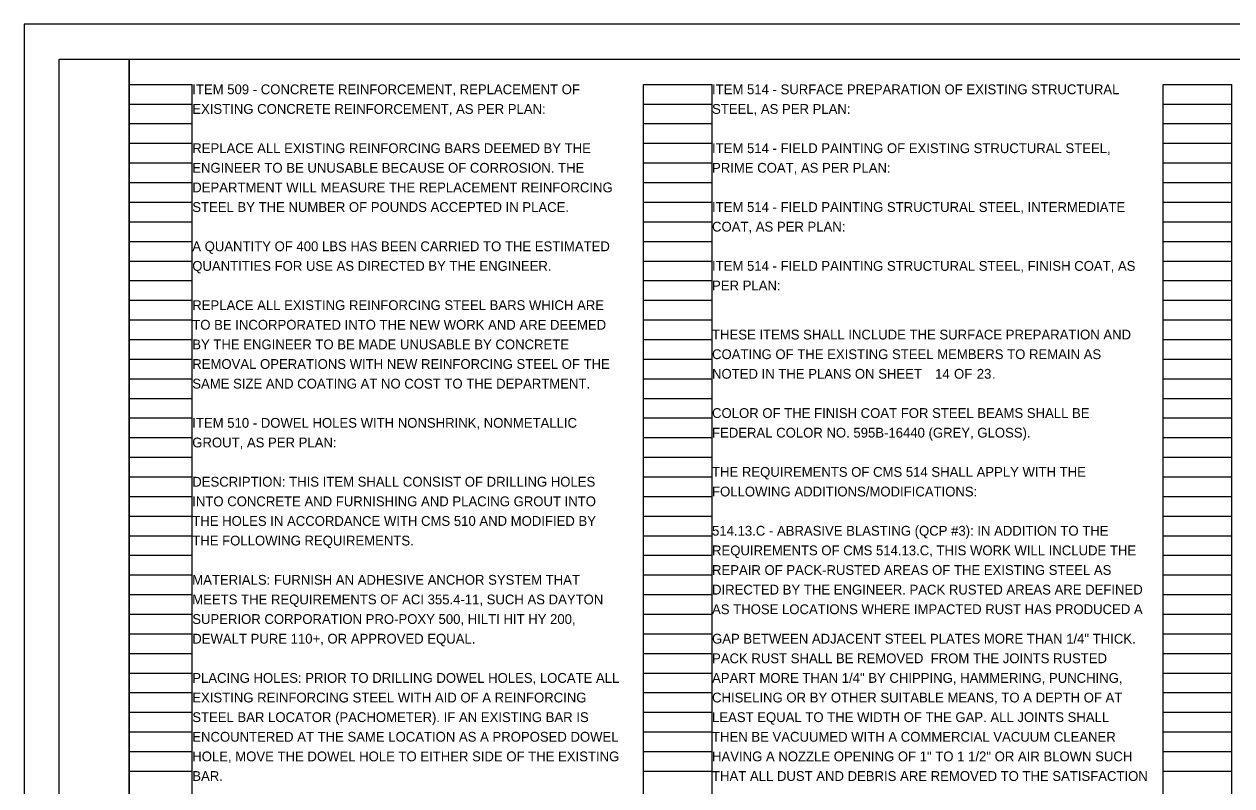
# Model space of a CAD drawing. Extents: x 0 to 34, y 0 to 22.
# Drawn here: x 0 to 17.24, y 11.13 to 22 of the extents above; entities that cross this region are included whole.
import ezdxf

# ---------------------------------------------------------------- set-up
doc = ezdxf.new("R2010")
doc.units = 0
for name, color, linetype in [('BR_P_Gen_Text', 7, 'Continuous'), ('SH_Border', 7, 'Continuous'), ('SH_Cut_Line', 7, 'Continuous'), ('SH_Data', 7, 'Continuous')]:
    doc.layers.add(name, color=color, linetype=linetype)

msp = doc.modelspace()

# ---------------------------------------------------------------- linework, layer by layer
at = {"layer": 'SH_Border'}
for points in [[(0.5, 21.5), (1.5, 21.5), (1.5, 0.5), (0.5, 0.5)], [(1.5, 21.5), (33.5, 21.5), (33.5, 0.5), (1.5, 0.5)]]:
    msp.add_lwpolyline(points, close=True, dxfattribs=at)
at = {"layer": 'SH_Cut_Line'}
msp.add_lwpolyline([(0, 0), (34, 0), (34, 22), (0, 22)], close=True, dxfattribs=at)
at = {"layer": 'SH_Data'}
for p, q in [((1.5, 0.98), (1.5, 21.14)), ((1.5, 21.14), (2.4, 21.14)), ((2.4, 0.98), (2.4, 21.14)), ((8.84, 0.98), (8.84, 21.14)), ((8.84, 21.14), (9.82, 21.14)), ((9.82, 0.98), (9.82, 21.14)), ((16.26, 0.98), (16.26, 21.14)), ((16.26, 21.14), (17.24, 21.14)), ((17.24, 0.98), (17.24, 21.14)), ((1.5, 20.86), (2.4, 20.86)), ((8.84, 20.86), (9.82, 20.86)), ((16.26, 20.86), (17.24, 20.86)), ((1.5, 20.58), (2.4, 20.58)), ((8.84, 20.58), (9.82, 20.58)), ((16.26, 20.58), (17.24, 20.58)), ((1.5, 20.3), (2.4, 20.3)), ((8.84, 20.3), (9.82, 20.3)), ((16.26, 20.3), (17.24, 20.3)), ((1.5, 20.02), (2.4, 20.02)), ((8.84, 20.02), (9.82, 20.02)), ((16.26, 20.02), (17.24, 20.02)), ((1.5, 19.74), (2.4, 19.74)), ((8.84, 19.74), (9.82, 19.74)), ((16.26, 19.74), (17.24, 19.74)), ((1.5, 19.46), (2.4, 19.46)), ((8.84, 19.46), (9.82, 19.46)), ((16.26, 19.46), (17.24, 19.46)), ((1.5, 19.18), (2.4, 19.18)), ((8.84, 19.18), (9.82, 19.18)), ((16.26, 19.18), (17.24, 19.18)), ((1.5, 18.9), (2.4, 18.9)), ((8.84, 18.9), (9.82, 18.9)), ((16.26, 18.9), (17.24, 18.9)), ((1.5, 18.62), (2.4, 18.62)), ((8.84, 18.62), (9.82, 18.62)), ((16.26, 18.62), (17.24, 18.62)), ((1.5, 18.34), (2.4, 18.34)), ((8.84, 18.34), (9.82, 18.34)), ((16.26, 18.34), (17.24, 18.34)), ((1.5, 18.06), (2.4, 18.06)), ((8.84, 18.06), (9.82, 18.06)), ((16.26, 18.06), (17.24, 18.06)), ((1.5, 17.78), (2.4, 17.78)), ((8.84, 17.78), (9.82, 17.78)), ((16.26, 17.78), (17.24, 17.78)), ((1.5, 17.5), (2.4, 17.5)), ((8.84, 17.5), (9.82, 17.5)), ((16.26, 17.5), (17.24, 17.5)), ((1.5, 17.22), (2.4, 17.22)), ((8.84, 17.22), (9.82, 17.22)), ((16.26, 17.22), (17.24, 17.22)), ((1.5, 16.94), (2.4, 16.94)), ((8.84, 16.94), (9.82, 16.94)), ((16.26, 16.94), (17.24, 16.94)), ((1.5, 16.66), (2.4, 16.66)), ((8.84, 16.66), (9.82, 16.66)), ((16.26, 16.66), (17.24, 16.66)), ((1.5, 16.38), (2.4, 16.38)), ((8.84, 16.38), (9.82, 16.38)), ((16.26, 16.38), (17.24, 16.38)), ((1.5, 16.1), (2.4, 16.1)), ((8.84, 16.1), (9.82, 16.1)), ((16.26, 16.1), (17.24, 16.1)), ((1.5, 15.82), (2.4, 15.82)), ((8.84, 15.82), (9.82, 15.82)), ((16.26, 15.82), (17.24, 15.82)), ((1.5, 15.54), (2.4, 15.54)), ((8.84, 15.54), (9.82, 15.54)), ((16.26, 15.54), (17.24, 15.54)), ((1.5, 15.26), (2.4, 15.26)), ((8.84, 15.26), (9.82, 15.26)), ((16.26, 15.26), (17.24, 15.26)), ((1.5, 14.98), (2.4, 14.98)), ((8.84, 14.98), (9.82, 14.98)), ((16.26, 14.98), (17.24, 14.98)), ((1.5, 14.7), (2.4, 14.7)), ((8.84, 14.7), (9.82, 14.7)), ((16.26, 14.7), (17.24, 14.7)), ((1.5, 14.42), (2.4, 14.42)), ((8.84, 14.42), (9.82, 14.42)), ((16.26, 14.42), (17.24, 14.42)), ((1.5, 14.14), (2.4, 14.14)), ((8.84, 14.14), (9.82, 14.14)), ((16.26, 14.14), (17.24, 14.14)), ((1.5, 13.86), (2.4, 13.86)), ((8.84, 13.86), (9.82, 13.86)), ((16.26, 13.86), (17.24, 13.86)), ((1.5, 13.58), (2.4, 13.58)), ((8.84, 13.58), (9.82, 13.58)), ((16.26, 13.58), (17.24, 13.58)), ((1.5, 13.3), (2.4, 13.3)), ((8.84, 13.3), (9.82, 13.3)), ((16.26, 13.3), (17.24, 13.3)), ((1.5, 13.02), (2.4, 13.02)), ((8.84, 13.02), (9.82, 13.02)), ((16.26, 13.02), (17.24, 13.02)), ((1.5, 12.74), (2.4, 12.74)), ((8.84, 12.74), (9.82, 12.74)), ((16.26, 12.74), (17.24, 12.74)), ((1.5, 12.46), (2.4, 12.46)), ((8.84, 12.46), (9.82, 12.46)), ((16.26, 12.46), (17.24, 12.46)), ((1.5, 12.18), (2.4, 12.18)), ((8.84, 12.18), (9.82, 12.18)), ((16.26, 12.18), (17.24, 12.18)), ((1.5, 11.9), (2.4, 11.9)), ((8.84, 11.9), (9.82, 11.9)), ((16.26, 11.9), (17.24, 11.9)), ((1.5, 11.62), (2.4, 11.62)), ((8.84, 11.62), (9.82, 11.62)), ((16.26, 11.62), (17.24, 11.62)), ((1.5, 11.34), (2.4, 11.34)), ((8.84, 11.34), (9.82, 11.34)), ((16.26, 11.34), (17.24, 11.34))]:
    msp.add_line(p, q, dxfattribs=at)

# ---------------------------------------------------------------- texts
at = {"layer": 'BR_P_Gen_Text'}
for s, p in [('ITEM 509 - CONCRETE REINFORCEMENT, REPLACEMENT OF ', (2.4, 21)), ('ITEM 514 - SURFACE PREPARATION OF EXISTING STRUCTURAL ', (9.82, 21)), ('EXISTING CONCRETE REINFORCEMENT, AS PER PLAN: ', (2.4, 20.72)), ('STEEL, AS PER PLAN:', (9.82, 20.72)), ('REPLACE ALL EXISTING REINFORCING BARS DEEMED BY THE ', (2.4, 20.16)), ('ITEM 514 - FIELD PAINTING OF EXISTING STRUCTURAL STEEL, ', (9.82, 20.16)), ('ENGINEER TO BE UNUSABLE BECAUSE OF CORROSION. THE ', (2.4, 19.88)), ('PRIME COAT, AS PER PLAN:', (9.82, 19.88)), ('DEPARTMENT WILL MEASURE THE REPLACEMENT REINFORCING ', (2.4, 19.6)), ('STEEL BY THE NUMBER OF POUNDS ACCEPTED IN PLACE. ', (2.4, 19.32)), ('ITEM 514 - FIELD PAINTING STRUCTURAL STEEL, INTERMEDIATE ', (9.82, 19.32)), ('COAT, AS PER PLAN:', (9.82, 19.04)), ('A QUANTITY OF 400 LBS HAS BEEN CARRIED TO THE ESTIMATED ', (2.4, 18.76)), ('QUANTITIES FOR USE AS DIRECTED BY THE ENGINEER.', (2.4, 18.48)), ('ITEM 514 - FIELD PAINTING STRUCTURAL STEEL, FINISH COAT, AS ', (9.82, 18.48)), ('PER PLAN:', (9.82, 18.2)), ('REPLACE ALL EXISTING REINFORCING STEEL BARS WHICH ARE ', (2.4, 17.92)), ('TO BE INCORPORATED INTO THE NEW WORK AND ARE DEEMED ', (2.4, 17.64)), ('THESE ITEMS SHALL INCLUDE THE SURFACE PREPARATION AND ', (9.82, 17.5)), ('BY THE ENGINEER TO BE MADE UNUSABLE BY CONCRETE ', (2.4, 17.36)), ('COATING OF THE EXISTING STEEL MEMBERS TO REMAIN AS ', (9.82, 17.22)), ('REMOVAL OPERATIONS WITH NEW REINFORCING STEEL OF THE ', (2.4, 17.08)), ('NOTED IN THE PLANS ON SHEET', (9.82, 16.94)), ('14', (13.005, 16.94)), (' OF ', (13.222, 16.94)), ('23', (13.599, 16.94)), ('SAME SIZE AND COATING AT NO COST TO THE DEPARTMENT.', (2.4, 16.8)), ('.', (13.817, 16.94)), ('ITEM 510 - DOWEL HOLES WITH NONSHRINK, NONMETALLIC ', (2.4, 16.24)), ('COLOR OF THE FINISH COAT FOR STEEL BEAMS SHALL BE ', (9.82, 16.38)), ('FEDERAL COLOR NO. 595B-16440 (GREY, GLOSS).', (9.82, 16.1)), ('GROUT, AS PER PLAN: ', (2.4, 15.96)), ('DESCRIPTION: THIS ITEM SHALL CONSIST OF DRILLING HOLES ', (2.4, 15.4)), ('THE REQUIREMENTS OF CMS 514 SHALL APPLY WITH THE ', (9.82, 15.54)), ('FOLLOWING ADDITIONS/MODIFICATIONS:', (9.82, 15.26)), ('INTO CONCRETE AND FURNISHING AND PLACING GROUT INTO ', (2.4, 15.12)), ('THE HOLES IN ACCORDANCE WITH CMS 510 AND MODIFIED BY ', (2.4, 14.84)), ('514.13.C - ABRASIVE BLASTING (QCP #3): IN ADDITION TO THE ', (9.82, 14.7)), ('THE FOLLOWING REQUIREMENTS.', (2.4, 14.56)), ('REQUIREMENTS OF CMS 514.13.C, THIS WORK WILL INCLUDE THE ', (9.82, 14.42)), ('MATERIALS: FURNISH AN ADHESIVE ANCHOR SYSTEM THAT ', (2.4, 14)), ('REPAIR OF PACK-RUSTED AREAS OF THE EXISTING STEEL AS ', (9.82, 14.14)), ('DIRECTED BY THE ENGINEER. PACK RUSTED AREAS ARE DEFINED ', (9.82, 13.86)), ('MEETS THE REQUIREMENTS OF ACI 355.4-11, SUCH AS DAYTON ', (2.4, 13.72)), ('AS THOSE LOCATIONS WHERE IMPACTED RUST HAS PRODUCED A ', (9.82, 13.58)), ('SUPERIOR CORPORATION PRO-POXY 500, HILTI HIT HY 200, ', (2.4, 13.44)), ('DEWALT PURE 110+, OR APPROVED EQUAL.', (2.4, 13.16)), ('GAP BETWEEN ADJACENT STEEL PLATES MORE THAN 1/4" THICK. ', (9.82, 13.16)), ('PACK RUST SHALL BE REMOVED  FROM THE JOINTS RUSTED ', (9.82, 12.88)), ('PLACING HOLES: PRIOR TO DRILLING DOWEL HOLES, LOCATE ALL ', (2.4, 12.6)), ('APART MORE THAN 1/4" BY CHIPPING, HAMMERING, PUNCHING, ', (9.82, 12.6)), ('EXISTING REINFORCING STEEL WITH AID OF A REINFORCING ', (2.4, 12.32)), ('CHISELING OR BY OTHER SUITABLE MEANS, TO A DEPTH OF AT ', (9.82, 12.32)), ('STEEL BAR LOCATOR (PACHOMETER). IF AN EXISTING BAR IS ', (2.4, 12.04)), ('LEAST EQUAL TO THE WIDTH OF THE GAP. ALL JOINTS SHALL ', (9.82, 12.04)), ('ENCOUNTERED AT THE SAME LOCATION AS A PROPOSED DOWEL ', (2.4, 11.76)), ('THEN BE VACUUMED WITH A COMMERCIAL VACUUM CLEANER ', (9.82, 11.76)), ('HOLE, MOVE THE DOWEL HOLE TO EITHER SIDE OF THE EXISTING ', (2.4, 11.48)), ('HAVING A NOZZLE OPENING OF 1" TO 1 1/2" OR AIR BLOWN SUCH ', (9.82, 11.48)), ('BAR. ', (2.4, 11.2)), ('THAT ALL DUST AND DEBRIS ARE REMOVED TO THE SATISFACTION ', (9.82, 11.2))]:
    msp.add_text(s, height=0.14, dxfattribs=at).set_placement(p)

doc.saveas('drawing.dxf')
